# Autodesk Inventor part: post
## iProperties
Shininess: 64.0
Length Units: 11269
Angle Units: 11279
Time Units: 11290
Mass Units: 11283
Length Display Precision: 3
Angle Display Precision: 2
Compacted: True
Part Number: post
Document SubType Name: Modeling
Created: 2004-10
Material: Standard
Designer: W. Holzwarth
Manufacturer: Standard
Standards Organization: Custom
Density: 0.0
Volumn: 0.0
Area: 0.0
PropertySet Name: Model Information
Control State: 0
Master: False
Checked Out: False
Author: W. Holzwarth
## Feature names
1. Basis1
